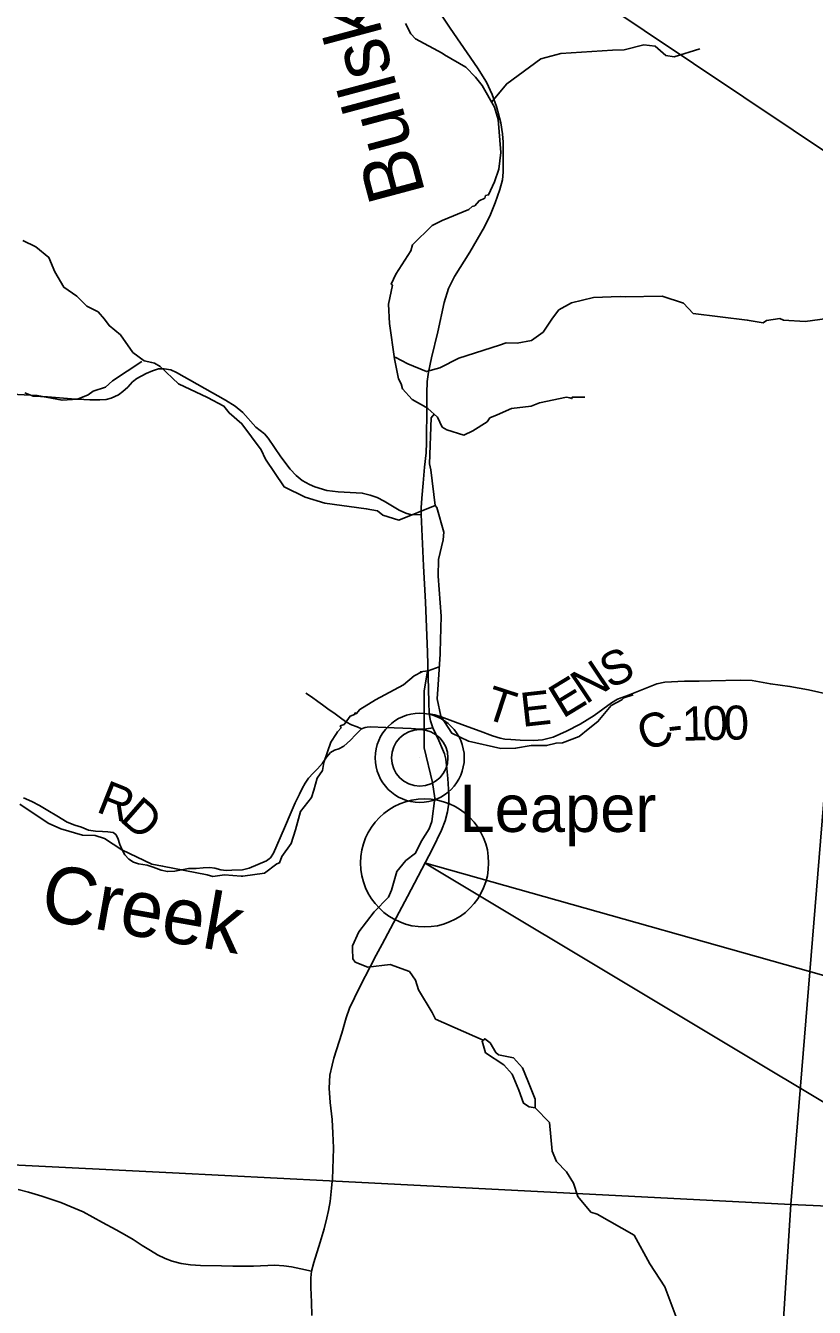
# Model space of a CAD drawing. Extents: x -1.8 to 75.7, y -2 to 25.
# Drawn here: x 4.973 to 6.292, y 16.983 to 19.123 of the extents above; entities that cross this region are included whole.
import ezdxf

# ---------------------------------------------------------------- set-up
doc = ezdxf.new("R2010")
doc.units = 0
for name, color, linetype in [('GM_X_County_Road', 7, 'Continuous'), ('GM_X_County_Road_Text', 7, 'Continuous'), ('GM_X_Minor_River', 7, 'Continuous'), ('GM_X_Minor_River_Text', 7, 'Continuous'), ('GM_X_State_Route', 7, 'Continuous'), ('GM_X_Township', 7, 'Continuous'), ('GM_X_Township_Road', 7, 'Continuous'), ('GM_X_Unincorporated', 7, 'Continuous'), ('GM_X_Unincorporated_Location', 7, 'Continuous'), ('GM_X_Unincorporated_Text', 7, 'Continuous'), ('TX_P_1', 7, 'Continuous')]:
    doc.layers.add(name, color=color, linetype=linetype)

msp = doc.modelspace()

# ---------------------------------------------------------------- linework, layer by layer
at = {"layer": 'GM_X_County_Road'}
for points in [[(4.9724, 18.5096), (4.9863, 18.504), (5.01, 18.5029), (5.0501, 18.4997), (5.0806, 18.498), (5.0973, 18.498), (5.1082, 18.4987), (5.1165, 18.5008), (5.1285, 18.5064), (5.1361, 18.5117), (5.144, 18.5194), (5.1522, 18.5282), (5.1594, 18.5339), (5.1748, 18.5418), (5.1852, 18.5465), (5.1957, 18.5497), (5.2047, 18.5499), (5.216, 18.5482), (5.2256, 18.5437), (5.3075, 18.4972), (5.3238, 18.4876), (5.3366, 18.4771), (5.3579, 18.4526), (5.3727, 18.441), (5.3788, 18.4338), (5.4, 18.403), (5.4156, 18.3823), (5.4256, 18.3717), (5.4358, 18.3635), (5.4476, 18.3567), (5.457, 18.3529), (5.477, 18.3469), (5.496, 18.3445), (5.536, 18.3422), (5.5492, 18.339), (5.5607, 18.3349), (5.5727, 18.3288), (5.5974, 18.314), (5.609, 18.3087), (5.6184, 18.3059), (5.6346, 18.3064)], [(5.6479, 17.9738), (5.6574, 17.9722), (5.6676, 17.9689), (5.7067, 17.9543), (5.7329, 17.9447), (5.7535, 17.937), (5.7663, 17.9332), (5.7744, 17.9317), (5.7842, 17.9307), (5.8, 17.93), (5.8228, 17.9293), (5.8373, 17.9304), (5.855, 17.9349), (5.8773, 17.9446), (5.9004, 17.9567), (5.9234, 17.9709), (5.9525, 17.9919), (5.9626, 17.9985), (5.9808, 18.0052), (6.0059, 18.0149), (6.0281, 18.0236), (6.0414, 18.0264), (6.0742, 18.0283), (6.0991, 18.0283), (6.1192, 18.0286), (6.1676, 18.03), (6.1875, 18.0293), (6.218, 18.0238), (6.2506, 18.0196), (6.2815, 18.0136), (6.321, 18.0052)], [(5.3877, 17.7413), (5.406, 17.7832), (5.4173, 17.8098), (5.4241, 17.8254), (5.4309, 17.8396), (5.4358, 17.8489), (5.4408, 17.8582), (5.4464, 17.8665), (5.454, 17.8749), (5.4613, 17.8817), (5.4697, 17.8914), (5.4765, 17.9013), (5.483, 17.9095), (5.4894, 17.9133), (5.497, 17.9153), (5.5054, 17.9198), (5.5162, 17.9298), (5.5246, 17.9386), (5.5302, 17.9442), (5.5345, 17.9485), (5.5411, 17.9512), (5.544, 17.9515)], [(5.544, 17.9515), (5.5491, 17.952), (5.5753, 17.9507), (5.6179, 17.9492), (5.6326, 17.9481), (5.6432, 17.9487), (5.6539, 17.9505)], [(4.9698, 17.8338), (4.9836, 17.8272), (4.9967, 17.8207), (5.0107, 17.8123), (5.0256, 17.8035), (5.043, 17.7931), (5.0559, 17.7877), (5.0669, 17.7843), (5.0787, 17.7796), (5.0902, 17.778), (5.1017, 17.7771), (5.111, 17.7769), (5.1196, 17.7755), (5.1243, 17.7721), (5.1275, 17.7662), (5.1311, 17.7556), (5.1347, 17.7466), (5.1394, 17.7384), (5.1462, 17.731), (5.1535, 17.7262), (5.1623, 17.7235), (5.1763, 17.7213), (5.1864, 17.7177), (5.2, 17.7129), (5.2104, 17.7104), (5.2228, 17.7111), (5.2458, 17.7154), (5.2583, 17.7154), (5.27, 17.7165), (5.2813, 17.7174), (5.2894, 17.7163), (5.2998, 17.7131), (5.3084, 17.712), (5.3181, 17.7125), (5.3358, 17.7134), (5.3469, 17.7161), (5.3757, 17.7283), (5.3825, 17.7333), (5.3875, 17.7409), (5.3877, 17.7413)]]:
    msp.add_lwpolyline(points, dxfattribs=at)
at = {"layer": 'GM_X_Minor_River'}
for points in [[(5.6085, 19.1264), (5.6172, 19.1093), (5.6247, 19.101), (5.6694, 19.0767), (5.6735, 19.0741), (5.7091, 19.0533), (5.725, 19.037), (5.7363, 19.0229), (5.7568, 18.9865), (5.7632, 18.9663), (5.7674, 18.9112), (5.7644, 18.8831), (5.7569, 18.8622), (5.7471, 18.8401), (5.7422, 18.8389), (5.7407, 18.8348), (5.7312, 18.8302), (5.7241, 18.8222), (5.7195, 18.8206), (5.7142, 18.8157), (5.6697, 18.7973), (5.653, 18.7893), (5.6202, 18.7569), (5.6172, 18.7466), (5.5919, 18.7078), (5.5843, 18.6911), (5.5866, 18.6892), (5.5798, 18.658), (5.5814, 18.6253), (5.5901, 18.5664), (5.5966, 18.5329), (5.6008, 18.5246), (5.6034, 18.5166), (5.6193, 18.4984), (5.642, 18.4859), (5.6458, 18.4836), (5.6617, 18.4689), (5.6696, 18.4525), (5.6772, 18.448), (5.7056, 18.4389), (5.7207, 18.4462), (5.7445, 18.4614), (5.7494, 18.4679), (5.7615, 18.4729), (5.7853, 18.4836), (5.8182, 18.4875), (5.8322, 18.4932), (5.8771, 18.5024), (5.8828, 18.5013), (5.8862, 18.5002), (5.887, 18.5025), (5.9077, 18.5025)], [(5.7519, 18.995), (5.7774, 19.0258), (5.8346, 19.0672), (5.8678, 19.0764), (5.9541, 19.0816), (5.9738, 19.0825), (6.0066, 19.0906), (6.0254, 19.0885), (6.0435, 19.0727), (6.0574, 19.0707), (6.1001, 19.0842)], [(5.6581, 18.3217), (5.5969, 18.2971), (5.5703, 18.3055), (5.5614, 18.3126), (5.5426, 18.3163), (5.4737, 18.3257), (5.4408, 18.3355), (5.4054, 18.353), (5.3743, 18.3991), (5.3672, 18.4146), (5.3349, 18.4581), (5.3135, 18.4763), (5.3047, 18.4876), (5.2776, 18.5017), (5.2291, 18.5245), (5.1983, 18.5536), (5.1886, 18.5593), (5.1841, 18.5602), (5.1717, 18.5632), (5.1525, 18.5771), (5.1318, 18.6063), (5.113, 18.6221), (5.105, 18.6326), (5.0944, 18.6447), (5.0758, 18.6544), (5.0593, 18.6709), (5.0374, 18.686), (5.0224, 18.7119), (5.0125, 18.7358), (4.9903, 18.7532), (4.9687, 18.7642)], [(5.5908, 18.5694), (5.6119, 18.5579), (5.6436, 18.5451), (5.6654, 18.5516), (5.6976, 18.5677), (5.7652, 18.5895), (5.7763, 18.5933), (5.7951, 18.5927), (5.8187, 18.5973), (5.8384, 18.6111), (5.8539, 18.6345), (5.8645, 18.6482), (5.8856, 18.6601), (5.9226, 18.6688), (5.9672, 18.6708), (5.9755, 18.6701), (6.0372, 18.6712), (6.0727, 18.6594), (6.0892, 18.6422), (6.1792, 18.6313), (6.2059, 18.6267), (6.2113, 18.6307), (6.2337, 18.6338), (6.2397, 18.6309), (6.2759, 18.6286), (6.3131, 18.6339)], [(5.1675, 18.5618), (5.1189, 18.53), (5.1069, 18.519), (5.0863, 18.5124), (5.0781, 18.5066), (5.0602, 18.4992), (5.0344, 18.4973), (4.9927, 18.5055), (4.9606, 18.5069), (4.917, 18.514), (4.879, 18.5087), (4.8504, 18.5127), (4.7854, 18.5505), (4.7454, 18.5415), (4.6761, 18.5346), (4.6307, 18.5345), (4.6243, 18.5359), (4.6049, 18.5433)], [(5.6562, 18.474), (5.6511, 18.4681), (5.6483, 18.3912)], [(5.6483, 18.3912), (5.6508, 18.3814), (5.6581, 18.3217), (5.6607, 18.3183), (5.6725, 18.2769), (5.6714, 18.2643), (5.6635, 18.2313), (5.6627, 18.2039), (5.6677, 18.137), (5.6663, 18.0769), (5.6659, 18.0735), (5.6626, 18.0229), (5.6611, 17.999), (5.6671, 17.9697), (5.6857, 17.9413), (5.7137, 17.928), (5.7674, 17.916), (5.7923, 17.9164), (5.818, 17.9207), (5.8441, 17.9207), (5.86, 17.9249), (5.8706, 17.9253), (5.8985, 17.9357), (5.9133, 17.9482), (5.9299, 17.9608), (5.9522, 17.9875), (5.9695, 17.997), (5.9733, 18.0005), (5.9888, 18.0054)], [(5.6645, 18.0524), (5.6463, 18.0453), (5.633, 18.0438), (5.6357, 18.0438), (5.6225, 18.0373), (5.6051, 18.022), (5.5579, 17.9972), (5.5318, 17.9812), (5.5258, 17.9736), (5.5242, 17.9755), (5.5231, 17.9724), (5.5156, 17.9697), (5.5057, 17.9557), (5.4993, 17.9537), (5.5005, 17.9503), (5.4948, 17.9438), (5.4929, 17.9412), (5.4835, 17.9263), (5.4718, 17.8925), (5.4695, 17.8792), (5.4609, 17.8666), (5.4552, 17.8461), (5.4514, 17.8343), (5.4326, 17.8107), (5.4243, 17.7802), (5.4171, 17.7574), (5.4016, 17.7357), (5.3975, 17.725), (5.3933, 17.7235), (5.3726, 17.7075), (5.3363, 17.7029), (5.3336, 17.7029), (5.3057, 17.7047), (5.2864, 17.7024), (5.2769, 17.705), (5.2024, 17.7196), (5.1843, 17.7226), (5.134, 17.7465), (5.1052, 17.7654), (5.0897, 17.7707), (5.0686, 17.7714), (5.0323, 17.7816), (5.0111, 17.7914), (4.9638, 17.8229)], [(5.6448, 18.0451), (5.6397, 18.012), (5.6397, 17.9497), (5.6394, 17.9171), (5.6536, 17.8593), (5.6573, 17.833), (5.652, 17.794), (5.6478, 17.782), (5.6343, 17.7608), (5.625, 17.7409), (5.6088, 17.7289), (5.5935, 17.7104), (5.5846, 17.6792), (5.5797, 17.6676), (5.5559, 17.6433), (5.53, 17.6099), (5.5198, 17.5863), (5.5197, 17.5814), (5.5203, 17.565), (5.5243, 17.5592), (5.5452, 17.5506), (5.5828, 17.5551), (5.6149, 17.5438), (5.6247, 17.529), (5.6299, 17.5129), (5.6529, 17.4754), (5.6586, 17.4642), (5.7381, 17.4288)], [(5.742, 17.408), (5.7724, 17.3876), (5.7867, 17.3724), (5.7976, 17.3454), (5.8056, 17.3235), (5.8149, 17.3175), (5.825, 17.3161), (5.8247, 17.3305), (5.8124, 17.3609), (5.804, 17.3828), (5.7886, 17.3993), (5.7638, 17.4046), (5.759, 17.4082), (5.75, 17.4244), (5.7408, 17.4312), (5.7361, 17.4271), (5.742, 17.408)], [(5.825, 17.3161), (5.8488, 17.2914), (5.8531, 17.2434), (5.8608, 17.2261), (5.8773, 17.2092), (5.8889, 17.1902), (5.8961, 17.168), (5.918, 17.1418), (5.9283, 17.1384)], [(5.9283, 17.1384), (5.9903, 17.1035), (6.0164, 17.0554), (6.0416, 17.0172), (6.0617, 16.9637), (6.072, 16.8928), (6.0782, 16.867), (6.0859, 16.8507)]]:
    msp.add_lwpolyline(points, dxfattribs=at)
at = {"layer": 'GM_X_State_Route'}
for points in [[(5.451, 17.0434), (5.455, 17.058), (5.4654, 17.0915), (5.4724, 17.1141), (5.4767, 17.1321), (5.4796, 17.1446), (5.4826, 17.1597), (5.4848, 17.1818), (5.4858, 17.1937), (5.486, 17.1956), (5.4866, 17.2146), (5.4873, 17.23), (5.488, 17.2494), (5.4866, 17.2735), (5.4857, 17.2966), (5.4824, 17.3246), (5.4806, 17.3488), (5.4819, 17.3707), (5.4855, 17.3872), (5.4885, 17.3987), (5.5016, 17.4405), (5.509, 17.466), (5.5147, 17.4821), (5.523, 17.4997), (5.5327, 17.5193), (5.5497, 17.5523), (5.5592, 17.5708), (5.569, 17.5893), (5.6116, 17.6686), (5.6536, 17.7486), (5.6686, 17.7793), (5.6744, 17.7951), (5.6787, 17.8101), (5.6809, 17.825), (5.6809, 17.8392), (5.6789, 17.8657), (5.6767, 17.8879), (5.6756, 17.8983), (5.6734, 17.9068), (5.6701, 17.9148), (5.6639, 17.9292), (5.6539, 17.9505), (5.6499, 17.962), (5.6479, 17.9738), (5.647, 17.994), (5.6448, 18.0765), (5.6417, 18.1604), (5.6381, 18.221), (5.6346, 18.3064), (5.6346, 18.3178), (5.6353, 18.3338), (5.6375, 18.3591), (5.6402, 18.3858), (5.6426, 18.4094), (5.6433, 18.4269), (5.6438, 18.4882), (5.6438, 18.5091), (5.6445, 18.5287), (5.6465, 18.544), (5.6518, 18.5681), (5.6625, 18.6116), (5.673, 18.6605), (5.68, 18.684), (5.6902, 18.7042), (5.7155, 18.7445), (5.7403, 18.7871), (5.7505, 18.8075), (5.7583, 18.8272), (5.766, 18.849), (5.7702, 18.8653), (5.7716, 18.8784), (5.7716, 18.9035), (5.7714, 18.9285), (5.7704, 18.9423), (5.7677, 18.9606), (5.7602, 18.9878), (5.7529, 19.0077), (5.7434, 19.0284), (5.7284, 19.0522), (5.6827, 19.1188), (5.6533, 19.1628)], [(4.9608, 17.1798), (4.9782, 17.1753), (5.0005, 17.1683), (5.0324, 17.1577), (5.0498, 17.1507), (5.0696, 17.1421), (5.1017, 17.1245), (5.1248, 17.1125), (5.1428, 17.1023), (5.153, 17.0964), (5.1684, 17.0861), (5.1819, 17.0775), (5.1939, 17.0705), (5.2065, 17.0646), (5.2183, 17.0599), (5.2332, 17.0562), (5.2488, 17.054), (5.2657, 17.0528), (5.3007, 17.0524), (5.3197, 17.0517), (5.3371, 17.0517), (5.3545, 17.0517), (5.39, 17.0531), (5.4049, 17.0524), (5.4178, 17.0504), (5.4331, 17.0472), (5.451, 17.0434)], [(5.4516, 16.9694), (5.4509, 16.9913), (5.4498, 17.0161), (5.4501, 17.032), (5.451, 17.0434)]]:
    msp.add_lwpolyline(points, dxfattribs=at)
at = {"layer": 'GM_X_Township'}
for points in [[(2.1, 17.3659), (3.1354, 17.3103), (3.6863, 17.2831), (4.4195, 17.2469), (4.6712, 17.2345), (5.2191, 17.2074), (5.4813, 17.1939), (6.252, 17.1543), (6.3199, 17.9861), (6.3212, 18.0078), (6.3226, 18.0577), (6.3233, 18.0805), (6.3259, 18.1065), (6.3299, 18.1515), (6.3889, 19.1678), (6.4185, 19.6642), (6.4493, 20.1816), (6.4874, 20.9)], [(6.4874, 20.9), (6.4493, 20.1816), (6.4185, 19.6642), (6.3889, 19.1678), (6.3299, 18.1515), (6.3259, 18.1065), (6.3233, 18.0805), (6.3226, 18.0577), (6.3212, 18.0078), (6.3199, 17.9861), (6.252, 17.1543), (7.1962, 17.1121), (7.3049, 17.1072), (8.4894, 17.0481), (8.8908, 17.028), (8.9, 17.0276)], [(6.0631, 14.1), (6.0891, 14.525), (6.1136, 14.9242), (6.1259, 15.1242), (6.1707, 15.8638), (6.1898, 16.179), (6.2265, 16.7539), (6.252, 17.1543), (5.4813, 17.1939), (5.2191, 17.2074), (4.6712, 17.2345), (4.4195, 17.2469), (3.6863, 17.2831), (3.1354, 17.3103), (2.1, 17.3659)], [(8.9, 17.0276), (8.8908, 17.028), (8.4894, 17.0481), (7.3049, 17.1072), (7.1962, 17.1121), (6.252, 17.1543), (6.2265, 16.7539), (6.1898, 16.179), (6.1707, 15.8638), (6.1259, 15.1242), (6.1136, 14.9242), (6.0891, 14.525), (6.0631, 14.1)]]:
    msp.add_lwpolyline(points, dxfattribs=at)
at = {"layer": 'GM_X_Township_Road'}
msp.add_lwpolyline([(5.5345, 17.9485), (5.5273, 17.9519), (5.5178, 17.9553), (5.5099, 17.9598), (5.5016, 17.9657), (5.4905, 17.9736), (5.4787, 17.9824), (5.4693, 17.989), (5.4616, 17.9944), (5.4512, 18.0021), (5.4417, 18.0084)], dxfattribs=at)
at = {"layer": 'GM_X_Unincorporated'}
for radius in [0.0744, 0.0472]:
    msp.add_circle((5.632, 17.9003), radius, dxfattribs=at)
at = {"layer": 'GM_X_Unincorporated_Location'}
msp.add_line((5.632, 17.9003), (5.632, 17.9003), dxfattribs=at)
at = {"layer": 'TX_P_1'}
msp.add_line((-1.8436, 24.3711), (37.5745, -2.0199), dxfattribs=at)
msp.add_lwpolyline([(6.4418, 17.2447), (5.6402, 17.7249), (6.4418, 17.499)], dxfattribs=at)
msp.add_circle((5.6402, 17.7249), 0.107, dxfattribs=at)

# ---------------------------------------------------------------- texts
at = {"layer": 'GM_X_County_Road_Text'}
for s, rotation, p in [('N', 33.8168, (5.9097, 17.9887)), ('S', 23.6824, (5.9489, 18.0153)), ('T', 341.992, (5.737, 17.9676)), ('E', 31.3233, (5.8711, 17.9652)), ('E', 6.3632, (5.8035, 17.9518)), ('C', 21.0284, (6.009, 17.9104)), ('1', 1.2465, (6.0707, 17.9288)), ('0', 1.2387, (6.1057, 17.9296)), ('0', 1.2308, (6.1407, 17.9303)), ('-', 6.6661, (6.0489, 17.9262)), ('R', 338.3562, (5.0896, 17.811)), ('D', 318.7764, (5.1286, 17.7964))]:
    msp.add_text(s, height=0.0568, rotation=rotation, dxfattribs=at).set_placement(p)
at = {"layer": 'GM_X_Minor_River_Text'}
for s, height, rotation, p in [('Bullskin', 0.09471, 105.0011, (5.6419, 18.8433)), ('Creek', 0.0947, 349.9986, (4.9951, 17.6314))]:
    msp.add_text(s, height=height, rotation=rotation, dxfattribs=at).set_placement(p)
at = {"layer": 'GM_X_Unincorporated_Text'}
msp.add_text('Leaper', height=0.07898, rotation=0, dxfattribs=at).set_placement((5.6986, 17.7766))

doc.saveas('drawing.dxf')
